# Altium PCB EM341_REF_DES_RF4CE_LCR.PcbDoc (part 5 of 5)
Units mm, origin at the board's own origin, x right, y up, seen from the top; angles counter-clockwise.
Board outline 218.38 x 83.13 mm, 2 copper layers (Top Layer, Carbon Ink Layer); 111 components, 91 nets, 369 pads, 80 vias.
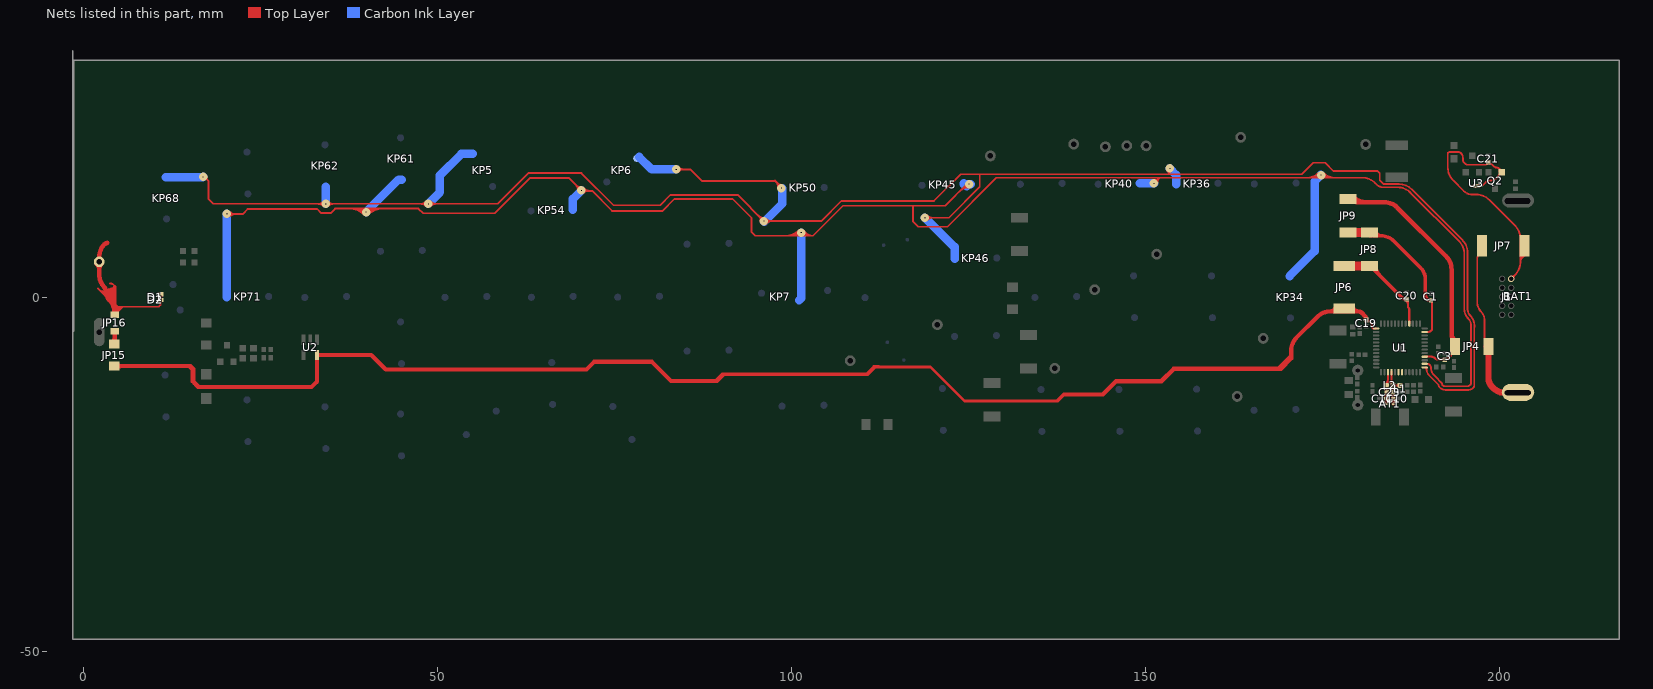
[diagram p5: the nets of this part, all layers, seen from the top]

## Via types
v1: diameter 1.2, hole 0, Top Layer to Carbon Ink Layer, 80 vias

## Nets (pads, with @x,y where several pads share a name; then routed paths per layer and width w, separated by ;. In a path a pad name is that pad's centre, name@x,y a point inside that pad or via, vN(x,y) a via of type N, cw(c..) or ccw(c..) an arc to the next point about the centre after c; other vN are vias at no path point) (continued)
PC6: KP5.1 KP6.2 KP36.1 KP46.2 KP50.2 KP62.2 KP68.2 U1.13 | length 330.2
  Top Layer w0.254: v1(16.87,16.96) 17.07,16.96 17.65,16.38 17.65,13.84 18.32,13.17 58.47,13.17 62.8,17.5 70.3,17.5 74.83,12.97 81.43,12.97 82.88,14.42 92.37,14.42 v1(96.07,10.72) 104.17,10.72 107.01,13.56 120.07,13.56 123.845,17.335 172.035,17.335 173.67,18.97 175.32,18.97 176.5,17.79 182.73,17.79 183.04,17.48 183.04,16.502 183.589,15.953 185.755,15.953 cw(c185.755,13.413) 187.551,15.209 188.826,13.934 188.829,13.934 194.689,8.074 cw(c192.893,6.278) 195.433,6.278 195.433,-1.651 ccw(c196.866,-1.651) 195.853,-2.665 cw(c194.54,-3.977) 196.396,-3.977 196.396,-4.243 ; v1(83.69,18.03) 85.69,18.03 87.32,16.4 97.68,16.4 v1@98.6,15.48 ; v1(118.81,11.2) 122.21,11.2 126.56,15.55 126.56,17.335 ; v1@119.144,10.866 cw(c119.952,10.058) 119.952,11.2 cw(c119.952,12.342) v1@119.144,11.534 ; 153.23,17.335 153.27,17.375 153.27,18.29 v1(153.4,18.16) ; U1.13@189.673,-9.912 cw(c189.642,-9.882) 189.642,-9.925 U1.13@189.378,-9.925 cw(c189.378,-10.249) 189.607,-10.02 cw(c189.522,-10.105) 189.643,-10.105 ccw(c191.07,-10.105) 190.061,-11.114 191.291,-12.344 cw(c191.098,-12.537) 191.371,-12.537 ccw(c191.607,-12.537) 191.44,-12.704 191.54,-12.804 ccw(c192.286,-12.058) 192.286,-13.113 194.743,-13.113 ; 194.76,-13.115 195.552,-13.115 ccw(c195.552,-12.185) 196.21,-12.842 ccw(c195.77,-12.402) 196.392,-12.402 196.392,-4.253 ; 84.832,18.03 cw(c84.832,19.172) 84.024,18.364 ccw(c84.832,19.172) 84.832,18.03 ; 84.832,18.03 ccw(c84.832,16.888) 84.024,17.696 cw(c84.832,16.888) 84.832,18.03 ; 95.263,11.527 cw(c94.455,10.72) 95.597,10.72 ccw(c94.455,10.72) 95.263,11.527 ; 95.263,11.527 ccw(c96.07,12.335) 96.07,11.193 cw(c96.07,12.335) 95.263,11.527 ; 97.212,10.72 cw(c97.212,11.862) 96.404,11.054 ccw(c97.212,11.862) 97.212,10.72 ; 97.212,10.72 ccw(c97.212,9.578) 96.404,10.386 cw(c97.212,9.578) 97.212,10.72 ; 153.27,17.364 cw(c153.623,17.364) 153.528,17.705 ccw(c153.623,17.364) 153.27,17.364 ; 153.27,17.364 ccw(c152.649,17.364) 153.075,17.816 cw(c152.649,17.364) 153.27,17.364 ; v1@16.92,16.747 cw(c17.044,16.219) 17.428,16.602 ccw(c17.044,16.219) v1@16.92,16.747 ; v1@17.343,16.96 ccw(c18.002,16.96) 17.536,16.494 cw(c18.002,16.96) v1@17.343,16.96 ; 33,13.17 cw(c33,11.96) 33.856,12.816 ccw(c33,11.96) 33,13.17 ; 33.096,13.17 ccw(c33.096,14.244) 33.856,13.484 cw(c33.096,14.244) 33.096,13.17 ; v1@34.524,12.816 cw(c35.38,11.96) 35.38,13.17 ccw(c35.38,11.96) v1@34.524,12.816 ; v1@34.524,13.484 ccw(c35.284,14.244) 35.284,13.17 cw(c35.284,14.244) v1@34.524,13.484 ; 47.514,13.17 cw(c47.514,11.994) 48.346,12.826 ccw(c47.514,11.994) 47.514,13.17 ; 47.562,13.17 ccw(c47.562,14.278) 48.346,13.494 cw(c47.562,14.278) 47.562,13.17 ; v1@49.014,12.826 cw(c49.846,11.994) 49.846,13.17 ccw(c49.846,11.994) v1@49.014,12.826 ; v1@49.014,13.494 ccw(c49.798,14.278) 49.798,13.17 cw(c49.798,14.278) v1@49.014,13.494 ; 97.636,16.444 cw(c96.573,15.38) 98.077,15.38 ccw(c96.573,15.38) 97.636,16.444 ; 97.999,16.081 ccw(c98.55,16.633) 98.55,15.853 cw(c98.55,16.633) 97.999,16.081 ; 98.07,16.01 cw(c97.44,15.38) 98.331,15.38 ccw(c97.44,15.38) 98.07,16.01
  Carbon Ink Layer w1.2: KP68.2@11.59,16.937 16.847,16.937 v1(16.87,16.96) ; v1@34.21,13.17 KP62.2@34.21,15.593 ; v1(48.68,13.16) 50.32,14.8 50.32,17.19 53.346,20.216 KP5.1@54.988,20.216 ; KP6.2@78.452,19.792 80.224,18.02 83.7,18.02 v1(83.69,18.03) ; v1@96.14,10.65 98.683,13.193 KP50.2@98.683,15.35 ; v1@118.81,11.19 123.047,6.953 ; KP46.2@123.053,5.38 123.053,7.13 ; v1(153.4,18.16) 153.4,18.13 154.28,17.25 KP36.1@154.28,15.94
  other v1: 34.19,13.15 98.55,15.38
PC7: KP7.2 KP34.2 KP40.2 KP45.2 KP54.2 KP61.2 KP71.2 U1.14 | length 355.5
  Top Layer w0.254: v1@20.634,11.386 cw(c21.442,10.578) 21.442,11.72 ; v1@20.634,12.054 ccw(c21.442,12.862) 21.442,11.72 ; 61.83,15.61 63.05,16.83 ; v1@69.817,15.06 ccw(c68.675,15.06) 69.483,15.867 ccw(c70.29,16.675) v1@70.29,15.533 ; v1(70.29,15.06) 68.52,16.83 63.05,16.83 ; v1@70.37,14.99 71.8,14.99 74.62,12.17 81.76,12.17 83.45,13.86 91.63,13.86 94.33,11.16 94.33,9.17 94.85,8.65 103,8.65 ; v1@70.445,15.215 ccw(c70.988,15.758) 70.988,14.99 ; v1@70.624,14.726 cw(c71.263,14.087) 71.263,14.99 ; v1@70.624,15.394 ccw(c71.601,16.371) 71.601,14.99 ; 117.11,12.89 117.11,10.71 117.89,9.93 121.99,9.93 128.907,16.847 180.586,16.847 cw(c180.586,14.307) 182.382,16.104 182.575,15.91 ccw(c183.568,16.903) 183.568,15.499 185.566,15.499 cw(c185.566,12.959) 187.362,14.755 194.235,7.883 cw(c192.439,6.087) 194.979,6.087 194.979,-1.75 ccw(c196.708,-1.75) 195.485,-2.973 cw(c194.411,-4.047) 195.93,-4.047 195.93,-4.565 ; 123.696,14.916 cw(c125.05,13.563) v1@125.05,15.477 ; 124.13,15.35 cw(c125.05,14.43) v1@125.05,15.731 ; 124.469,15.689 ccw(c124.208,15.95) v1@124.577,15.95 ; v1@125.24,15.96 124.74,15.96 121.67,12.89 107.24,12.89 103,8.65 ; v1(151.15,16.05) 151.14,16.06 151.173,16.06 151.96,16.847 ; v1(174.74,17.23) v1@174.75,17.23 ; U1.14@189.378,-9.425 189.704,-9.425 cw(c189.704,-10.014) 190.12,-9.597 cw(c189.776,-9.942) 190.262,-9.942 ccw(c191.834,-9.942) 190.357,-10.479 ccw(c191.834,-9.942) 190.638,-10.961 ccw(c191.834,-9.942) 190.723,-11.053 190.917,-11.248 ; 190.915,-11.25 191.743,-12.078 cw(c191.478,-12.343) 191.83,-12.215 cw(c191.478,-12.343) 191.852,-12.327 cw(c191.478,-12.343) 191.852,-12.343 191.86,-12.35 ccw(c191.999,-12.35) 191.901,-12.448 ccw(c192.261,-12.088) 192.261,-12.598 194.682,-12.598 ; 194.683,-12.602 195.351,-12.602 ccw(c195.351,-11.954) 195.81,-12.413 ccw(c195.522,-12.124) 195.929,-12.124 195.929,-4.553 ; 21.442,11.72 22.45,11.72 23.16,12.43 33,12.43 33.57,11.86 34.89,11.86 35.52,12.49 47.28,12.49 47.94,11.83 58.05,11.83 63.05,16.83 ; 103,8.65 cw(c103,10.131) 101.742,9.35 ccw(c103,10.131) 103,8.65 ; 151.96,16.847 cw(c151.176,17.631) 151.158,16.523 ccw(c151.176,17.631) 151.96,16.847 ; 37.575,12.49 cw(c37.575,9.675) 39.566,11.666 ccw(c37.575,9.675) 37.575,12.49 ; 38.188,12.49 cw(c38.188,10.288) 39.745,11.845 ccw(c38.188,10.288) 38.188,12.49 ; 38.802,12.49 cw(c38.802,10.902) 39.925,12.025 ccw(c38.802,10.902) 38.802,12.49 ; 39.415,12.49 cw(c39.415,11.515) 40.104,12.204 ccw(c39.415,11.515) 39.415,12.49 ; v1@39.696,12.204 cw(c40.385,11.515) 40.385,12.49 ccw(c40.385,11.515) v1@39.696,12.204 ; v1@39.875,12.025 cw(c40.998,10.902) 40.998,12.49 ccw(c40.998,10.902) v1@39.875,12.025 ; v1@40.055,11.845 cw(c41.612,10.288) 41.612,12.49 ccw(c41.612,10.288) v1@40.055,11.845 ; v1@40.234,11.666 cw(c42.225,9.675) 42.225,12.49 ccw(c42.225,9.675) v1@40.234,11.666 ; 99.112,8.65 ccw(c99.112,11.328) 101.006,9.434 cw(c99.112,11.328) 99.112,8.65 ; 99.725,8.65 ccw(c99.725,10.715) 101.185,9.255 cw(c99.725,10.715) 99.725,8.65 ; 100.338,8.65 ccw(c100.338,10.102) 101.365,9.075 cw(c100.338,10.102) 100.338,8.65 ; v1@101.31,9.082 ccw(c102.086,9.564) 102.086,8.65 cw(c102.086,9.564) v1@101.31,9.082 ; v1@101.526,9.216 ccw(c102.543,9.847) 102.543,8.65 cw(c102.543,9.847) v1@101.526,9.216 ; v1@151.623,16.05 cw(c152.735,16.05) 151.949,16.836 ccw(c152.735,16.05) v1@151.623,16.05 ; 172.675,16.847 ccw(c172.675,19.295) 174.406,17.564 cw(c172.675,19.295) 172.675,16.847 ; 173.288,16.847 ccw(c173.288,18.682) 174.585,17.385 cw(c173.288,18.682) 173.288,16.847 ; 173.901,16.847 ccw(c173.901,18.069) 174.765,17.205 cw(c173.901,18.069) 173.901,16.847 ; v1@174.715,17.205 ccw(c175.579,18.069) 175.579,16.847 cw(c175.579,18.069) v1@174.715,17.205 ; v1@174.895,17.385 ccw(c176.192,18.682) 176.192,16.847 cw(c176.192,18.682) v1@174.895,17.385 ; v1@175.074,17.564 ccw(c176.805,19.295) 176.805,16.847 cw(c176.805,19.295) v1@175.074,17.564
  Carbon Ink Layer w1.2: KP71.2@20.233,-0.04 v1@20.233,11.76 ; v1(39.9,12) 44.483,16.583 KP61.2@44.9,16.583 ; KP54.2@69.11,12.31 69.097,12.31 69.097,13.867 v1(70.29,15.06) ; KP7.2@101.026,-0.466 101.34,-0.151 v1(101.34,9.1) ; KP45.2@124.68,15.66 124.297,16.043 124.297,15.96 v1@125.25,15.96 ; KP40.2@149.177,16.06 151.15,16.06 151.16,16.05 v1(151.15,16.05) ; KP34.2@170.3,2.957 173.83,6.487 173.83,16.34 174.73,17.24 v1(174.74,17.23)
  other v1: 20.24,11.76 125.05,15.95
RF_N: AT1.2 C10.1 C23.2 L1.1 L2.1 U1.4 | length 14.5
  Top Layer w0.292: U1.4@184.703,-10.49 U1.4@184.703,-10.6 184.703,-12.078 ; L2.1@184.744,-12.372 ccw(c184.53,-12.252) 184.703,-12.078 ; L2.1@184.917,-12.475 184.931,-12.489 L1.1@185.898,-12.489 ; L2.1@185.03,-12.405 184.703,-12.078 ; 184.703,-12.078 ccw(c184.905,-12.078) L2.1@184.903,-12.28 ; 184.703,-12.078 ccw(c184.905,-12.078) L2.1@184.903,-12.28 ; 184.703,-12.078 ccw(c184.905,-12.078) L2.1@184.903,-12.28 ; 184.703,-11.551 ccw(c185.808,-11.551) L2.1@185.027,-12.332 ; 184.703,-11.551 ccw(c185.808,-11.551) L2.1@185.027,-12.332 ; 184.703,-11.551 ccw(c185.808,-11.551) L2.1@185.027,-12.332 ; L2.1@185.027,-12.611 cw(c185.32,-12.904) 185.32,-12.489 ; L2.1@185.027,-12.611 cw(c185.32,-12.904) 185.32,-12.489 ; L2.1@185.027,-12.611 cw(c185.32,-12.904) 185.32,-12.489 ; L2.1@185.027,-12.357 ccw(c185.344,-12.04) 185.344,-12.489 ; L2.1@185.027,-12.357 ccw(c185.344,-12.04) 185.344,-12.489 ; L2.1@185.027,-12.357 ccw(c185.344,-12.04) 185.344,-12.489 ; 185.441,-12.489 cw(c185.441,-12.921) L1.1@185.746,-12.616 ; 185.441,-12.489 ccw(c185.441,-12.057) L1.1@185.746,-12.362 ; 185.441,-12.489 cw(c185.441,-12.921) L1.1@185.746,-12.616 ; 185.441,-12.489 ccw(c185.441,-12.057) L1.1@185.746,-12.362 ; 185.441,-12.489 ccw(c185.441,-12.057) L1.1@185.746,-12.362 ; 185.441,-12.489 cw(c185.441,-12.921) L1.1@185.746,-12.616
  Top Layer w0.508: C10.1@184.9,-14.182 L2.1@184.9,-12.484 L2.1@184.9,-12.475 ; AT1.2@184.95,-15.092 184.95,-14.405 C10.1@185.017,-14.337 ; 184.9,-13.987 ccw(c185.354,-13.987) C10.1@185.033,-14.307 ; 184.9,-13.987 ccw(c185.354,-13.987) C10.1@185.033,-14.307 ; 184.9,-13.987 ccw(c185.354,-13.987) C10.1@185.033,-14.307
RF_P: AT1.1 C11.1 C23.1 L2.2 U1.3 | length 10.2
  Top Layer w0.292: L2.2@184.002,-12.263 184.203,-12.062 ; U1.3@184.203,-10.62 184.203,-12.062 ; L2.2@183.874,-12.332 ccw(c183.078,-11.537) 184.203,-11.537 ; L2.2@183.874,-12.332 ccw(c183.078,-11.537) 184.203,-11.537 ; L2.2@183.874,-12.332 ccw(c183.078,-11.537) 184.203,-11.537 ; L2.2@183.993,-12.28 ccw(c183.985,-12.062) 184.203,-12.062 ; L2.2@183.993,-12.28 ccw(c183.985,-12.062) 184.203,-12.062 ; L2.2@183.993,-12.28 ccw(c183.985,-12.062) 184.203,-12.062 ; L2.2@184.158,-12.374 cw(c184.39,-12.248) 184.203,-12.062 ; L2.2@184.158,-12.374 cw(c184.39,-12.248) 184.203,-12.062 ; L2.2@184.158,-12.374 cw(c184.39,-12.248) 184.203,-12.062
  Top Layer w0.508: C11.1@183.935,-14.248 184,-14.182 L2.2@184,-12.484 L2.2@184,-12.425 ; AT1.1@183.945,-15.021 183.945,-14.24 C11.1@183.998,-14.188 ; C11.1@183.866,-14.309 ccw(c183.543,-13.986) 184,-13.986 ; C11.1@183.866,-14.309 ccw(c183.543,-13.986) 184,-13.986 ; C11.1@183.866,-14.309 ccw(c183.543,-13.986) 184,-13.986
TX_ALT_N: U1.7
TX_ALT_P: U1.6
VDD: BAT1.1 JP4.1 JP7.2 pad.22 pad.23 pad.24 pad.25 pad.26 pad.27 pad.28 pad.29 pad.30 pad.31 pad.32 pad.33 pad.34 pad.35 pad.36 pad.37 pad.38 pad.39 pad.40 pad.41 pad.42 pad.43 pad.44 pad.45 pad.46 pad.47 pad.48 pad.49 pad.50 | length 41.1
  Top Layer w0.254: JP7.2@196.905,8.587 ccw(c197.024,8.587) 196.94,8.502 cw(c196.481,8.044) 197.13,8.044 197.13,6.102 ccw(c197.94,5.293) 196.795,5.293 196.795,-0.652 ccw(c198.956,-0.652) 197.427,-2.18 cw(c196.498,-3.11) 197.812,-3.11 197.812,-5.606 ccw(c198.491,-5.606) 198.011,-6.086 cw(c197.115,-6.983) JP4.1@198.382,-6.983 ; JP7.2@196.952,8.591 cw(c196.038,7.678) JP7.2@197.33,7.678
  Top Layer w0.6: BAT1.1@202.25,-13.475 BAT1.1@202.3,-13.475
  Top Layer w0.635: BAT1.1@201.925,-13.613 BAT1.1@202,-13.613 ; BAT1.1@201.358,-13.442 ccw(c201.771,-13.029) BAT1.1@201.771,-13.613 ; BAT1.1@201.358,-13.442 ccw(c201.771,-13.029) BAT1.1@201.771,-13.613 ; BAT1.1@201.358,-13.442 ccw(c201.771,-13.029) BAT1.1@201.771,-13.613 ; BAT1.1@201.358,-13.442 ccw(c201.771,-13.029) BAT1.1@201.771,-13.613 ; BAT1.1@201.433,-13.442 ccw(c201.846,-13.029) BAT1.1@201.846,-13.613 ; BAT1.1@201.433,-13.442 ccw(c201.846,-13.029) BAT1.1@201.846,-13.613 ; BAT1.1@201.433,-13.442 ccw(c201.846,-13.029) BAT1.1@201.846,-13.613 ; BAT1.1@201.433,-13.442 ccw(c201.846,-13.029) BAT1.1@201.846,-13.613 ; BAT1.1@202.129,-13.613 ccw(c202.129,-13.029) BAT1.1@202.542,-13.442 ; BAT1.1@202.129,-13.613 ccw(c202.129,-13.029) BAT1.1@202.542,-13.442 ; BAT1.1@202.129,-13.613 ccw(c202.129,-13.029) BAT1.1@202.542,-13.442 ; BAT1.1@202.129,-13.613 ccw(c202.129,-13.029) BAT1.1@202.542,-13.442
  Top Layer w0.762: BAT1.1@202.425,-13.456 BAT1.1@202.556,-13.456
  Top Layer w0.889: JP4.1@198.145,-6.973 198.145,-6.981 JP4.1@198.146,-6.995 ; JP4.1@198.437,-6.965 ccw(c198.57,-7.098) 198.382,-7.098 198.382,-11.377 ccw(c200.303,-11.377) 198.945,-12.735 198.999,-12.789 ccw(c200.795,-10.993) 200.795,-13.533 201.6,-13.533 BAT1.1@201.885,-13.533 ; BAT1.1@201.36,-13.64 BAT1.1@201.375,-13.655 ; BAT1.1@201.375,-13.303 BAT1.1@201.53,-13.303 ; BAT1.1@201.731,-13.303 cw(c201.731,-13.869) BAT1.1@202.131,-13.469 ; BAT1.1@201.731,-13.303 cw(c201.731,-13.869) BAT1.1@202.131,-13.469 ; BAT1.1@201.731,-13.303 cw(c201.731,-13.869) BAT1.1@202.131,-13.469 ; BAT1.1@201.731,-13.303 cw(c201.731,-13.869) BAT1.1@202.131,-13.469 ; BAT1.1@201.881,-13.303 cw(c201.881,-13.869) BAT1.1@202.281,-13.469 ; BAT1.1@201.881,-13.303 cw(c201.881,-13.869) BAT1.1@202.281,-13.469 ; BAT1.1@201.881,-13.303 cw(c201.881,-13.869) BAT1.1@202.281,-13.469 ; BAT1.1@201.881,-13.303 cw(c201.881,-13.869) BAT1.1@202.281,-13.469 ; BAT1.1@201.931,-13.303 cw(c201.931,-13.869) BAT1.1@202.331,-13.469 ; BAT1.1@201.931,-13.303 cw(c201.931,-13.869) BAT1.1@202.331,-13.469 ; BAT1.1@201.931,-13.303 cw(c201.931,-13.869) BAT1.1@202.331,-13.469 ; BAT1.1@201.931,-13.303 cw(c201.931,-13.869) BAT1.1@202.331,-13.469 ; BAT1.1@201.931,-13.303 cw(c201.931,-13.869) BAT1.1@202.331,-13.469 ; BAT1.1@201.931,-13.303 cw(c201.931,-13.869) BAT1.1@202.331,-13.469 ; BAT1.1@201.931,-13.303 cw(c201.931,-13.869) BAT1.1@202.331,-13.469 ; BAT1.1@201.931,-13.303 cw(c201.931,-13.869) BAT1.1@202.331,-13.469 ; BAT1.1@201.556,-13.303 cw(c201.556,-13.869) 201.956,-13.469 ccw(c201.556,-13.869) BAT1.1@201.556,-13.303 ; BAT1.1@201.631,-13.303 cw(c201.631,-13.869) 202.031,-13.469 ccw(c201.631,-13.869) BAT1.1@201.631,-13.303
VDD_1: JP15.2 JP16.1 | length 4.3
  Top Layer w0.635: JP16.1@4.365,-4.812 4.365,-6.494 ccw(c4.433,-6.494) JP15.2@4.385,-6.542 ; JP15.2@4.107,-6.41 ccw(c3.485,-5.788) 4.365,-5.788 cw(c3.485,-5.788) JP15.2@4.107,-6.41 ; 4.365,-5.897 ccw(c5.091,-5.897) 4.578,-6.41 cw(c5.091,-5.897) 4.365,-5.897
VDD_2: JP16.2 pad.0@2.2,4.975 | length 32.9
  Top Layer w0.254: 1.99,1.22 4.31,-1.1 4.31,-1.74 ; 2.61,0.86 2.79,0.68 2.79,0.57 ; 3.45,0.22 3.45,1.01 ; 3.56,-0.06 3.56,1.14 ; 3.69,0.18 3.7,0.19 3.7,1.13 ; 3.7,-0.23 3.7,0.42 ; 3.7,1.91 3.94,1.91 4.01,1.84 4.13,1.84 4.52,1.45 JP16.2@4.52,-2.203 ; 3.89,-0.27 3.89,1.19 ; 4.06,-0.57 4.06,1.26 ; 4.3,-0.96 4.3,1.52
  Top Layer w0.635: pad.0@2.2,4.975 2.2,3.187 ccw(c4.74,3.187) 2.944,1.391 cw(c2.609,1.057) 3.083,1.057 ccw(c5.338,1.057) 3.743,-0.538 cw(c2.344,-1.937) 4.323,-1.937 JP16.2@4.323,-2.55 ; pad.0@2.207,5.01 2.207,5.665 cw(c4.747,5.665) 2.951,7.461 2.955,7.465 cw(c3.371,7.049) 3.371,7.638 ; 2.2,3.902 cw(c3.273,3.902) 2.514,4.661 ccw(c3.273,3.902) 2.2,3.902 ; 2.2,3.902 ccw(c1.127,3.902) 1.886,4.661 cw(c1.127,3.902) 2.2,3.902
VDD_3: C1.1 JP8.2 JP9.1 U1.23 | length 24.8
  Top Layer w0.292: U1.23@189.378,-4.925 189.853,-4.925 ccw(c189.853,-4.268) 190.318,-4.733 ccw(c190.025,-4.44) 190.438,-4.44 190.438,-1.015 ccw(c189.565,-1.015) C1.1@190.183,-0.397
  Top Layer w0.508: JP8.2@181.522,9.02 ccw(c182.422,9.919) 182.422,8.648 183.226,8.648 ; 189.482,2.525 ccw(c187.267,2.525) 188.834,4.092 185.022,7.904 ccw(c183.226,6.108) 183.226,8.648 ; 189.483,2.525 189.483,0.22 ccw(c190.137,0.22) 189.675,-0.242 ccw(c190.049,0.132) 190.049,-0.397 C1.1@190.183,-0.397 ; 183.226,8.648 cw(c183.226,9.403) 182.496,9.208 ccw(c183.226,9.403) 183.226,8.648
  Top Layer w1.27: JP9.1@178.597,9.128 181.573,9.128 cw(c181.573,8.948) JP8.2@181.7,9.075
VDD_4: C3.1 JP4.2 JP9.2 U1.16 | length 41.2
  Top Layer w0.292: U1.16@189.378,-8.425 190.299,-8.425 cw(c190.299,-9.176) 190.83,-8.645 ccw(c191.283,-8.192) 191.283,-8.832 C3.1@192.213,-8.832 ; C3.1@192.202,-8.828 ccw(c192.202,-8.519) 192.42,-8.737 192.429,-8.729 cw(c192.83,-9.13) 192.523,-8.652 ccw(c192.523,-8.157) 192.874,-8.507 193.034,-8.348 ccw(c192.934,-8.247) 193.075,-8.247 ccw(c192.984,-8.157) 193.112,-8.157 193.112,-7.827 cw(c193.539,-7.827) JP4.2@193.238,-7.525 ; 191.818,-8.832 ccw(c191.818,-8.444) 192.093,-8.719 cw(c191.818,-8.444) 191.818,-8.832 ; 191.843,-8.832 cw(c191.843,-9.187) 192.093,-8.936 ccw(c191.843,-9.187) 191.843,-8.832
  Top Layer w0.635: JP9.2@178.788,13.745 179.008,13.745 cw(c179.008,12.823) 179.575,13.55 cw(c179.008,12.823) 179.66,13.475 ccw(c179.901,13.716) 179.901,13.375 ; JP4.2@193.682,-6.983 193.682,-6.605 ccw(c192.445,-6.605) 193.32,-5.73 cw(c193.677,-5.373) 193.172,-5.373 193.172,3.933 ccw(c190.632,3.933) 192.428,5.729 185.526,12.631 ccw(c183.73,10.835) 183.73,13.375 179.901,13.375 ; 179.901,13.375 cw(c179.901,13.841) 179.435,13.839 ccw(c179.901,13.841) 179.901,13.375 ; JP9.2@179.323,14.108 ccw(c181.093,15.878) 181.093,13.375 cw(c181.093,15.878) JP9.2@179.323,14.108
VDD_5: C19.1 JP6.2 JP15.1 U1.37 U2.5 | length 389.5
  Top Layer w0.254: 11.04,-9.745 14.895,-9.745 15.53,-10.38 15.53,-12.27 ; 12.58,-9.745 12.755,-9.57 15.17,-9.57 15.71,-10.11 15.71,-11.89 16.36,-12.54 ; 12.93,-9.92 14.85,-9.92 15.24,-10.31 15.24,-11.98 16.14,-12.88 16.96,-12.88 ; 15.59,-10.23 15.06,-9.7 15.05,-9.7 15.4,-10.05 15.4,-11.81 16.13,-12.54 ; 15.8,-12.54 16.7,-12.54 16.87,-12.71 17.12,-12.71 ; 16.11,-12.69 16.23,-12.69 ; 29.66,-12.7 29.7,-12.7 29.69,-12.71 ; 89.19,-11.74 90.13,-10.8 110.49,-10.8 111.55,-9.74 112.36,-9.74 112.41,-9.79 ; 89.25,-12.02 89.47,-12.02 90.45,-11.04 110.73,-11.04 111.81,-9.96 119.63,-9.96 124.43,-14.76 137.57,-14.76 138.33,-14 ; 89.33,-11.85 90.14,-11.04 ; 90.01,-10.92 110.55,-10.92 111.68,-9.79 119.6,-9.79 124.38,-14.57 137.41,-14.57 138.4,-13.58 143.84,-13.58 145.73,-11.69 152.12,-11.69 153.86,-9.95 169.24,-9.95 169.24,-9.72 170.35,-8.61 ; 140.13,-13.92 144.02,-13.92 145.86,-12.08 152.24,-12.08 154.01,-10.31 169.15,-10.31 170.71,-8.75 170.71,-7.49 ; 140.14,-13.8 143.94,-13.8 145.84,-11.9 152.28,-11.9 154.03,-10.15 ; 152.09,-11.9 153.84,-10.15 169.04,-10.15 170.54,-8.65 170.54,-7.529 ; 168.64,-9.95 170.37,-8.22 ; 168.9,-9.91 170.37,-8.44 170.37,-7.38
  Top Layer w0.292: C19.1@181.22,-3.41 181.462,-3.41 ; U1.37@182.528,-4.425 182.12,-4.425 181.996,-4.301 cw(c182.107,-4.19) 181.95,-4.19 181.95,-4.048 ccw(c181.302,-4.048) 181.76,-3.59 181.664,-3.493 ccw(c181.462,-3.695) 181.462,-3.41 ; 181.462,-3.41 cw(c181.462,-3.213) 181.268,-3.24 ccw(c181.462,-3.213) 181.462,-3.41 ; 182.05,-4.355 ccw(c182.211,-4.194) 182.228,-4.421 cw(c182.211,-4.194) 182.05,-4.355
  Top Layer w0.5: 137.79,-14.36 138.35,-13.8 140.14,-13.8
  Top Layer w0.6: JP15.1@4.343,-9.745 13.475,-9.745 ; 16.44,-12.71 29.69,-12.71 ; 21.12,-12.7 32.2,-12.7 32.954,-11.946 U2.5@32.954,-8.187 40.617,-8.187 42.66,-10.23 71.01,-10.23 72.09,-9.15 80.25,-9.15 82.95,-11.85 89.33,-11.85 ; 170.54,-7.529 cw(c173.08,-7.529) 171.284,-5.733 174.243,-2.774 cw(c176.039,-4.57) 176.039,-2.03 ; C19.1@181.118,-3.161 ccw(c181.094,-3.137) C19.1@181.127,-3.137 ; C19.1@181.165,-3.227 ccw(c180.374,-3.227) 180.933,-2.668 180.486,-2.221 ccw(c180.025,-2.682) 180.025,-2.03 ; 5.287,-9.745 cw(c5.287,-8.9) 4.69,-9.498 ccw(c5.287,-8.9) 5.287,-9.745 ; 5.287,-9.745 ccw(c5.287,-10.59) 4.69,-9.992 cw(c5.287,-10.59) 5.287,-9.745 ; 176.039,-2.03 ccw(c176.039,-1.175) 176.842,-1.47 cw(c176.039,-1.175) 176.039,-2.03 ; 176.039,-2.03 180.025,-2.03 ; 180.025,-2.03 cw(c180.025,-1.133) 179.19,-1.461 ccw(c180.025,-1.133) 180.025,-2.03 ; 180.861,-2.596 cw(c180.246,-3.21) C19.1@181.115,-3.21 ; 180.861,-2.596 cw(c180.246,-3.21) C19.1@181.115,-3.21 ; 180.861,-2.596 cw(c180.246,-3.21) C19.1@181.115,-3.21 ; 180.861,-2.596 cw(c180.246,-3.21) C19.1@181.115,-3.21
VDD_6: C20.1 JP6.1 JP8.1 U1.28 | length 20.3
  Top Layer w0.292: JP6.1@178.018,4.393 cw(c178.018,2.618) JP6.1@179.272,3.873 ; C20.1@187.022,-0.457 187.022,-1.334 ccw(c187.321,-1.334) 187.11,-1.545 cw(c186.885,-1.77) 187.203,-1.77 U1.28@187.203,-3.75 ; C20.1@186.731,-0.421 cw(c186.028,-1.125) 187.022,-1.125 ccw(c186.028,-1.125) C20.1@186.731,-0.421
  Top Layer w0.508: JP8.1@181.484,4.393 ccw(c181.947,4.43) 181.619,4.101 181.718,4.002 cw(c181.718,3.09) 182.363,3.735 186.177,-0.079 ccw(c186.704,0.447) 186.704,-0.298 C20.1@186.868,-0.298 ; JP8.1@182.511,4.393 ccw(c184.455,4.393) 183.08,3.018 cw(c184.455,4.393) JP8.1@182.511,4.393
  Top Layer w0.635: JP6.1@177.995,4.012 ccw(c177.995,4.132) JP6.1@178.08,4.048
  Top Layer w1.27: JP6.1@178.018,4.393 181.484,4.393 181.524,4.393 ccw(c181.524,4.461) JP8.1@181.572,4.413
VDD_7: D1.1 D1.4 D2.1 | length 22.5
  Top Layer w0.254: 4.3,-0.81 4.85,-1.36 6.22,-1.36 ; 4.34,-1.36 7.43,-1.36 ; 4.59,-2.3 5.53,-1.36 6.38,-1.36 ; 4.6,-1.82 4.88,-1.54 4.68,-1.54 4.53,-1.69 4.53,-2.1 5.27,-1.36 5.34,-1.36 ; 6.68,-1.36 7.98,-1.36 ; 7.73,-1.36 10.61,-1.36 10.85,-1.12 D1.1@10.85,0.4 ; D1.4@10.728,-0.522 cw(c10.432,-0.818) 10.85,-0.818 ; D1.4@10.728,-0.522 cw(c10.432,-0.818) 10.85,-0.818 ; D1.4@10.728,-0.522 cw(c10.432,-0.818) 10.85,-0.818 ; D1.4@10.728,-0.522 cw(c10.432,-0.818) 10.85,-0.818 ; D1.4@10.728,-0.278 ccw(c10.432,0.018) 10.85,0.018 ; D1.4@10.728,-0.278 ccw(c10.432,0.018) 10.85,0.018 ; D1.4@10.728,-0.278 ccw(c10.432,0.018) 10.85,0.018 ; D1.4@10.728,-0.278 ccw(c10.432,0.018) 10.85,0.018 ; 10.85,-0.818 cw(c11.268,-0.818) D1.4@10.972,-0.522 ; 10.85,-0.818 cw(c11.268,-0.818) D1.4@10.972,-0.522 ; 10.85,-0.818 cw(c11.268,-0.818) D1.4@10.972,-0.522 ; 10.85,-0.818 cw(c11.268,-0.818) D1.4@10.972,-0.522 ; 10.85,-0.018 cw(c11.268,-0.018) 10.972,0.278 ccw(c11.268,-0.018) 10.85,-0.018 ; 10.85,-0.018 ccw(c10.432,-0.018) 10.728,0.278 cw(c10.432,-0.018) 10.85,-0.018 ; 10.85,0.018 ccw(c11.268,0.018) D1.4@10.972,-0.278 ; 10.85,0.018 ccw(c11.268,0.018) D1.4@10.972,-0.278 ; 10.85,0.018 ccw(c11.268,0.018) D1.4@10.972,-0.278 ; 10.85,0.018 ccw(c11.268,0.018) D1.4@10.972,-0.278
  Top Layer w0.508: D1.1@10.855,0.221 cw(c11.077,0.221) D1.1@10.92,0.377
VDD_8: C21.1 J1.1 JP7.1 Q2.1 U3.3 | length 52.1
  Top Layer w0.254: 196.488,14.477 196.505,14.477 ; 196.488,14.49 196.067,14.49 cw(c196.067,16.132) 195.388,14.637 cw(c196.067,16.132) 194.906,14.971 193.394,16.483 cw(c195.19,18.279) 192.65,18.279 192.65,20.33 cw(c192.693,20.33) 192.662,20.36 cw(c192.946,20.076) 192.946,20.478 194.157,20.478 cw(c194.157,20.017) 194.482,20.342 194.502,20.323 cw(c193.849,19.67) 194.773,19.67 194.773,19.394 ccw(c195.421,19.394) 194.963,18.935 ccw(c195.596,19.569) 195.596,18.673 197.875,18.673 ccw(c197.875,19.287) 198.31,18.853 198.323,18.865 cw(c198.382,18.806) 198.382,18.89 cw(c198.382,18.105) 198.937,18.66 199.14,18.458 ccw(c199.562,18.88) 199.562,18.283 cw(c199.562,17.89) 199.84,18.168 200.035,17.972 cw(c198.417,17.972) 199.561,16.829 cw(c198.665,17.725) 198.665,16.458 ccw(c198.665,15.492) 197.982,16.175 197.639,15.831 cw(c197.267,16.203) U3.3@197.267,15.677 ; 196.505,14.475 196.69,14.475 cw(c196.69,11.935) 197.22,14.419 cw(c196.69,11.935) 198.487,13.731 202.149,10.069 cw(c200.352,8.273) 202.892,8.273 202.892,4.925 cw(c200.352,4.925) 202.149,3.129 J1.1@201.585,2.565 ; U3.3@196.722,15.66 cw(c196.765,15.618) 196.765,15.677 U3.3@197.267,15.677 ; 199.795,18.212 cw(c199.397,17.814) Q2.1@199.951,17.71 ; 199.869,18.139 ccw(c200.268,18.538) Q2.1@200.268,17.973 ; U3.3@197.267,15.677 cw(c197.267,16.011) 197.024,15.783 ccw(c197.267,16.011) U3.3@197.267,15.677 ; U3.3@197.267,15.677 ccw(c197.267,15.389) 197.036,15.562 cw(c197.267,15.389) U3.3@197.267,15.677 ; J1.1@201.585,2.888 ccw(c201.585,3.668) 202.136,3.116 ; J1.1@201.585,2.888 ccw(c201.585,3.668) 202.136,3.116 ; J1.1@201.585,2.888 ccw(c201.585,3.668) 202.136,3.116 ; J1.1@201.908,2.565 cw(c202.688,2.565) 202.136,3.116 ; J1.1@201.908,2.565 cw(c202.688,2.565) 202.136,3.116 ; J1.1@201.908,2.565 cw(c202.688,2.565) 202.136,3.116 ; 202.892,4.818 cw(c204.041,4.818) 203.662,5.902 ccw(c204.041,4.818) 202.892,4.818 ; 202.892,5.176 cw(c203.916,5.176) 203.578,6.141 ccw(c203.916,5.176) 202.892,5.176 ; 202.892,5.534 cw(c203.791,5.534) 203.494,6.381 ccw(c203.791,5.534) 202.892,5.534 ; JP7.1@202.892,5.891 cw(c203.665,5.891) 203.41,6.621 ccw(c203.665,5.891) JP7.1@202.892,5.891
pads on no net: D1.3
copper on no net: | length 4
  Top Layer w0.254: 18.699,-11.73 20.27,-11.73 ; 26.425,-11.725 26.425,-11.125 26.425,-9.3

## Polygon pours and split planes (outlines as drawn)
VDD on Top Layer "Top Layer-VDD" (solid, remove dead copper, pour order 2): 0.7,9.675 0.7,0 5.35,0 5.35,11.775 2.5,11.775 0.6,9.875
NetD3_K on Top Layer "Top Layer-NetD3_K" (solid, remove dead copper, pour order 4): 1.08,-0.482 1.08,-8.557 3.605,-8.557 3.605,-0.357
GND on Top Layer "Top Layer-No Net" (solid, remove dead copper, pour order 5): 153.123,-25.336 189.725,-25.336 cw(c189.725,-25.464) 189.815,-25.373 195.3,-23.303 201.433,-19.223 206.31,-14.251 206.255,14.907 201.148,19.899 198.13,22.007 194.655,24.077 189.89,25.937 189.89,16.862 196.648,8.872 196.668,-10.453 153.123,-10.453

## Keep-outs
Keep-Out Layer:
  circle w0.127: c128.463,12.855 r1.5
  circle w0.127: c39.756,-12.973 r1.5
  circle w0.127: c141.752,-8.552 r1.15
  circle w0.127: c28.906,9.267 r1.15
  circle w0.127: c141.752,8.586 r1.15
  circle w0.127: c28.906,-9.213 r1.15
  lines w0.127: 195.852,23.209 194.067,24.111 192.476,24.818 191.018,25.392 189.421,25.946 142.959,25.946 ; 195.875,23.2 197.975,21.975 ; 197.973,21.973 201,19.829 ; 7.235,19.638 13.753,23.598 ; 7.235,19.638 0.016,9.938 0.016,-9.904 7.208,-19.568 13.753,-23.544 22.692,-25.889 64.47,-25.889 94.832,-21.614 ; 7.235,19.638 13.753,23.598 ; 13.753,23.598 22.703,25.946 ; 13.753,23.598 22.703,25.946 ; 22.703,25.946 64.308,25.946 94.832,21.648 ; 94.832,-21.614 94.832,-21.008 ; 94.832,-21.614 94.832,-21.008 ; 94.832,-21.008 100.336,-20.233 ; 94.832,-21.008 100.336,-20.233 ; 94.832,21.042 94.832,21.648 ; 94.832,21.042 100.358,20.264 ; 94.832,21.042 100.358,20.264 ; 94.832,21.042 94.832,21.648 ; 100.336,-20.233 105.817,-20.611 ; 100.336,-20.233 105.817,-20.611 ; 100.358,20.264 105.817,20.638 ; 100.358,20.264 105.817,20.638 ; 105.817,-21.513 105.817,-20.611 ; 105.817,-21.513 105.817,-20.611 ; 105.817,-21.513 124.105,-22.774 141.19,-25.889 189.491,-25.889 ; 105.817,20.638 105.817,21.542 ; 105.817,20.638 105.817,21.542 ; 105.817,21.542 124.064,22.8 ; 105.817,21.542 124.064,22.8 ; 124.064,22.8 138.28,25.391 ; 124.064,22.8 138.28,25.391 ; 138.28,25.391 142.959,25.946 ; 138.28,25.391 142.959,25.946 ; 189.491,-25.889 189.986,-25.725 ; 189.491,-25.889 189.986,-25.725 ; 189.986,-25.725 190.641,-25.496 ; 189.986,-25.725 190.641,-25.496 ; 190.641,-25.496 191.286,-25.258 ; 190.641,-25.496 191.286,-25.258 ; 191.286,-25.258 191.922,-25.01 192.549,-24.753 193.167,-24.487 193.777,-24.212 194.377,-23.929 194.969,-23.637 195.552,-23.336 196.126,-23.026 196.692,-22.708 197.25,-22.382 197.799,-22.048 198.34,-21.704 198.872,-21.353 199.396,-20.993 199.912,-20.625 200.418,-20.247 200.916,-19.862 201.406,-19.467 201.886,-19.064 202.358,-18.651 202.821,-18.23 203.274,-17.8 203.719,-17.361 204.155,-16.913 204.581,-16.456 204.999,-15.989 205.406,-15.513 205.804,-15.027 206.167,-14.563 206.167,-1.983 205.056,-1.983 cw(c205.056,0.017) 205.056,2.017 206.167,2.017 206.167,14.597 205.939,14.89 ; 201,19.829 205.939,14.89 ; 201,19.829 205.939,14.89
  text "Keep-Out Layer" at 1.495,-37.765 h2

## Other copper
Top Layer:
  rectangle net GND: 204.58,2.32 205.11,2.97
  region net GND: 206,2.28 206,5.56 205.11,5.56 205.11,2.28
  rectangle net GND: 204.35,-2.95 205.99,-2.24
  rectangle net GND: 110.71,-21.103 111.213,-20.69
  rectangle net GND: 111.14,-21.201 112.215,-20.78
  rectangle net GND: 126.33,-22.53 127.45,-22.13
  rectangle net GND: 121.41,-21.903 121.93,-21.55
  rectangle net GND: 124.66,-22.18 125.77,-21.6
  rectangle net GND: 121.768,-21.891 128.57,-20.91
  rectangle net GND: 127.99,-22.78 128.59,-22.43
  rectangle net GND: 118.38,-21.683 118.881,-21.38
  rectangle net GND: 112.65,-21.23 114.15,-20.9
  rectangle net GND: 116.24,-21.48 118.98,-20.6
  rectangle net GND: 113.97,-21.32 116.5,-20.88
  rectangle net GND: 112.087,-20.769 114.13,-19.23
  rectangle net GND: 114.41,-20.13 114.76,-19.72
  rectangle net GND: 114.76,-20.5 117.51,-20.13
  rectangle net GND: 114.71,-20.29 115.08,-20.07
  rectangle net GND: 114.38,-20.5 114.91,-19.84
  rectangle net GND: 118.74,-21.74 122.15,-20.58
  rectangle net GND: 125.24,-20.63 125.78,-20.06
  rectangle net GND: 125.08,-21.13 126.08,-20.34
  rectangle net GND: 125.77,-20.99 126.32,-20.53
  rectangle net GND: 117.087,-20.3 117.46,-19.593
  rectangle net GND: 117.25,-19.87 117.6,-19.36
  rectangle net GND: 112.472,-21.05 125.53,-20.2
  rectangle net GND: 3.451,-11.83 4.58,-11.368
  rectangle net GND: 9.52,-8.7 14.75,-7.9
  rectangle net GND: 11.195,-8.09 11.55,-7.465
  rectangle net GND: 11.637,-8.24 13.27,-7.023
  rectangle net GND: 12.67,-8.15 13.78,-6.15
  rectangle net GND: 10.97,-8.01 11.41,-7.69
  rectangle net GND: 11.41,-8.01 11.85,-7.25
  rectangle net GND: 11.904,-7.45 12.38,-6.756
  rectangle net GND: 12.09,-7.19 12.51,-6.55
  rectangle net GND: 12.273,-7.54 13.01,-6.557
  rectangle net GND: 12.424,-6.77 12.93,-6.236
  rectangle net GND: 12.7,-6.47 13.24,-5.96
  rectangle net GND: 12.958,-6.31 13.58,-5.702
  rectangle net GND: 13.19,-5.95 13.66,-5.47
  rectangle net GND: 14.49,-8.57 14.88,-8.39
  rectangle net GND: 14.59,-8.5 14.95,-8.17
  rectangle net GND: 14.75,-8.37 15.08,-8.09
  rectangle net GND: 14.42,-7.944 15.506,-7.6
  rectangle net GND: 14.75,-8.27 15.16,-7.9
  rectangle net GND: 14.92,-8.108 15.342,-7.79
  rectangle net GND: 15.42,-7.83 15.64,-7.66
  rectangle net GND: 27.25,-6.61 30.98,-5.33
  rectangle net GND: 13.417,-8.11 14.51,-5.243
  rectangle net GND: 14.19,-7.74 15.71,-5.223
  rectangle net GND: 58.67,-24.982 65.044,-23.9
  rectangle net GND: 14.07,-22.17 17.098,-20.799
  rectangle net GND: 12.909,-21.335 17.001,-20.346
  rectangle net GND: 11.88,-20.699 16.49,-19.16
  rectangle net GND: 77.879,-22.1 78.72,-21.463
  rectangle net GND: 77.344,-21.98 77.71,-21.773
  rectangle net GND: 77.552,-21.98 78.15,-21.653
  rectangle net GND: 77.71,-21.98 78.15,-21.561
  rectangle net GND: 78.136,-21.77 80.29,-21.313
  rectangle net GND: 78.307,-21.52 78.626,-21.214
  rectangle net GND: 78.626,-21.52 78.99,-21.028
  rectangle net GND: 78.453,-21.45 78.87,-21.129
  rectangle net GND: 78.87,-21.45 79.26,-20.886
  rectangle net GND: 79.083,-21.42 79.83,-20.763
  rectangle net GND: 83.76,-21.851 85.809,-20.89
  rectangle net GND: 85.65,-21.613 87.492,-20.96
  rectangle net GND: 79.488,-21.82 84.13,-20.527
  rectangle net GND: 79.316,-20.99 79.73,-20.628
  rectangle net GND: 79.739,-20.96 80.4,-20.382
  rectangle net GND: 79.907,-20.84 80.7,-20.284
  rectangle net GND: 80.08,-20.71 80.6,-20.184
  rectangle net GND: 80.4,-20.96 81.12,-19.997
  rectangle net GND: 80.215,-20.84 80.7,-20.105
  rectangle net GND: 83.66,-21.277 89.871,-20.46
  rectangle net GND: 89.32,-21.16 91.69,-20.54
  rectangle net GND: 88.83,-20.742 93.662,-19.92
  rectangle net GND: 80.802,-20.92 81.46,-19.764
  rectangle net GND: 80.642,-20.5 81.34,-19.857
  rectangle net GND: 81.12,-20.96 89.55,-19.44
  rectangle net GND: 80.983,-20.41 81.48,-19.659
  rectangle net GND: 107.3,-20.75 111.93,-19.76
  rectangle net GND: 109.04,-20.925 112.18,-20.53
  rectangle net GND: 106.75,-20.707 107.383,-20.19
  rectangle net GND: 107.12,-20.58 107.63,-20
  rectangle net GND: 8.01,-18.309 8.91,-17.203
  rectangle net GND: 7.45,-18.07 8.25,-16.61
  rectangle net GND: 10.61,-20.05 14.57,-18.55
  rectangle net GND: 5.19,-14.6 5.93,-12.3
  rectangle net GND: 6.13,-13.92 6.679,-13.01
  rectangle net GND: 5.99,-13.91 6.562,-12.623
  rectangle net GND: 4.8,-13.98 5.54,-12.07
  rectangle net GND: 5.932,-15.698 6.449,-12.248
  rectangle net GND: 5.6,-14.93 6.335,-11.869
  rectangle net GND: 6.235,-16.107 7.04,-13.7
  rectangle net GND: 6.63,-15.91 7.335,-14.607
  rectangle net GND: 6.63,-15.67 7.186,-14.282
  rectangle net GND: 6.07,-16.19 6.82,-13.48
  rectangle net GND: 6.38,-13.87 6.749,-13.243
  rectangle net GND: 4.49,-13.41 5.11,-12.19
  rectangle net GND: 4.38,-13.27 5.13,-12.39
  rectangle net GND: 6.81,-16.39 7.45,-14.859
  rectangle net GND: 6.7,-15.34 7.261,-14.446
  rectangle net GND: 82.136,-20.21 93.785,-18.705
  rectangle net GND: 81.414,-19.67 81.708,-19.337
  rectangle net GND: 81.528,-19.61 81.97,-19.237
  rectangle net GND: 81.708,-19.67 82.53,-19.079
  rectangle net GND: 81.977,-19.49 82.48,-18.844
  rectangle net GND: 81.854,-19.29 82.16,-18.952
  rectangle net GND: 82.449,-19.15 82.78,-18.431
  rectangle net GND: 82.29,-19.15 82.78,-18.57
  rectangle net GND: 82.61,-19.23 83.34,-18.29
  rectangle net GND: 82.78,-19.15 83.65,-18.04
  rectangle net GND: 82.99,-18.45 98.34,-17.75
  rectangle net GND: 98.34,-18.57 98.78,-18.18
  rectangle net GND: 97.92,-18.32 98.5,-17.85
  rectangle net GND: 123.42,-22.01 124.51,-21.65
  rectangle net GND: 124.33,-22.159 124.707,-21.71
  rectangle net GND: 125.44,-22.34 128.8,-21.57
  rectangle net GND: 128.49,-22.91 137.25,-20.91
  rectangle net GND: 127.17,-22.67 128.77,-22.11
  rectangle net GND: 115.5,-21.5 116.355,-21.13
  rectangle net GND: 117.79,-21.662 118.589,-21.37
  rectangle net GND: 126.05,-21.01 126.447,-20.787
  rectangle net GND: 133.94,-23.89 134.34,-23.62
  rectangle net GND: 132.825,-23.704 133.496,-22.79
  rectangle net GND: 131.69,-23.44 133.05,-22.64
  rectangle net GND: 135.78,-24.33 137.07,-23.96
  rectangle net GND: 137.46,-24.54 137.76,-24.34
  rectangle net GND: 136.64,-24.502 137.023,-24.11
  rectangle net GND: 134.34,-24.03 135.18,-23.59
  rectangle net GND: 133.35,-23.79 135.32,-22.55
  rectangle net GND: 135.105,-24.138 136.93,-22.73
  rectangle net GND: 112.093,-21.239 112.738,-20.382
  rectangle net GND: 113.99,-20.59 114.583,-19.573
  rectangle net GND: 113.91,-19.92 114.44,-19.3
  rectangle net GND: 117.13,-21.02 125.78,-20.06
  rectangle net GND: 125.53,-20.51 125.91,-20.19
  rectangle net GND: 116.91,-20.39 117.28,-19.74
  rectangle net GND: 117.43,-20.6 117.83,-19.25
  rectangle net GND: 116.61,-20.39 116.91,-20.07
  rectangle net GND: 116.73,-20.3 117.087,-19.89
  rectangle net GND: 137.64,-24.67 138.18,-24.38
  rectangle net GND: 137.94,-24.748 138.311,-24.38
  rectangle net GND: 136.93,-24.485 141.6,-22.73
  rectangle net GND: 138.18,-24.67 139.07,-24.4
  rectangle net GND: 138.25,-23.19 157.05,-22.01
  rectangle net GND: 140.2,-25.174 140.553,-24.89
  rectangle net GND: 141.33,-25.366 141.559,-25.14
  rectangle net GND: 140.39,-25.21 141.54,-24.87
  rectangle net GND: 138.54,-24.879 139.002,-24.5
  rectangle net GND: 139.54,-24.99 140.02,-24.78
  rectangle net GND: 138.97,-24.89 140.2,-24.36
  rectangle net GND: 140.02,-24.99 141.64,-24.33
  rectangle net GND: 141.45,-25.44 152.96,-22.73
  rectangle net GND: 152.97,-24.13 156.49,-22.73
  rectangle net GND: 149.86,-22.27 150.22,-21.97
  rectangle net GND: 149.93,-22.12 150.24,-21.82
  rectangle net GND: 150.37,-22.23 150.74,-21.4
  rectangle net GND: 150.08,-22.16 150.62,-21.58
  rectangle net GND: 150.56,-22.47 151.21,-21.22
  rectangle net GND: 150.74,-22.23 151.35,-20.98
  rectangle net GND: 151.01,-22.43 151.98,-20.76
  rectangle net GND: 151.12,-21.02 152.02,-20.36
  rectangle net GND: 151.576,-22.54 152.72,-19.944
  rectangle net GND: 151.96,-20.13 152.77,-19.47
  rectangle net GND: 152.442,-22.61 155.19,-19.078
  rectangle net GND: 152.61,-19.18 153.3,-18.82
  rectangle net GND: 152.98,-19.5 153.59,-18.53
  rectangle net GND: 152.83,-19.34 153.26,-18.68
  rectangle net GND: 153.15,-19.74 153.91,-18.32
  rectangle net GND: 153.34,-19.64 154.14,-18.06
  rectangle net GND: 153.59,-19.18 154.11,-17.92
  rectangle net GND: 153.76,-19.62 154.98,-17.66
  rectangle net GND: 154.57,-22.42 157.33,-16.95
  rectangle net GND: 153.985,-18 154.35,-17.535
  rectangle net GND: 154.112,-17.99 154.47,-17.408
  rectangle net GND: 154.24,-17.98 154.66,-17.27
  rectangle net GND: 154.37,-18.11 154.98,-17.04
  rectangle net GND: 3.597,-12.546 6.23,-11.52
  rectangle net GND: 97.1,-18.76 98.623,-18.033
  rectangle net GND: 125.28,-20.23 125.61,-19.92
  rectangle net GND: 110.867,-20.75 111.93,-19.661
  rectangle net GND: 83.29,-19.5 97.42,-18.08
  rectangle net GND: 172.9,12.51 176.87,15.11
  rectangle net PA5: 148.763,4.703 152.543,6.383
  rectangle net PC3: 153.43,-7.97 164.18,-6.61
  rectangle net GND: 146.238,-14.88 146.86,-13.372
  rectangle net GND: 145.62,-14.88 146.44,-13.95
  region net VDD_2: 1.45,8.3 4.65,9.875 4.65,2.65 4.65,1.375 3.9,0.825 1.7,0.825 1.45,1.375 1.45,1.675 1.45,2.15 1.45,3.025
  text "Top Layer" at 1.495,-37.765 h2
Carbon Ink Layer:
  text "Carbon Ink Layer over Top Layer" at 1.495,-37.765 h2
Multi-Layer:
  text "EM341_REF_DES_RF4CE_LCR_A0" at 130.05,-37.34 h2
  text "EM341 Dipole Antenna RF4CE 1-Layer Remote Control" at 130.05,-41.44 h2

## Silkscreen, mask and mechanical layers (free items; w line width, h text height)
Top Overlay:
  drawing of 4891 lines, arcs and shapes, not listed
  text "JP24" at 179.57,22.91 h0.8
  text "JP25" at 142.246,22.72 h0.8
  text "JP21" at 145.38,22.71 h0.8
  text "JP22" at 148.98,22.71 h0.8
  text "JP27" at 138.37,22.66 h0.8
  text "JP23" at 159.27,21.92 h0.8
  text "JP26" at 129.44,19.92 h0.8
  text "Top Overlay" at 1.495,-37.765 h2
Bottom Overlay:
  text "Bottom Overlay" at 1.495,-37.765 h2
Top Paste:
  text "Top Paste" at 1.495,-37.765 h2
Bottom Paste:
  text "Bottom Paste" at 1.495,-37.765 h2
Top Solder:
  text "Top Solder" at 1.495,-37.765 h2
Bottom Solder:
  text "Bottom Solder" at 1.495,-37.765 h2
Mechanical 1:
  drawing of 406 lines, arcs and shapes, not listed
  text "SMD LED" at 7.35,-6 h0.8
  text "1608" at 8.55,-7.3 h0.8
  text "Top Assembly" at 1.495,-38.095 h2
Mechanical 2:
  lines w0.254: 108.18,-9.06 119.93,7.69 125.68,15.09 127.93,19.88 ; 120.58,-4.05 130.65,12.2 139.62,21.59 ; 137.34,-9 139.043,-1.45 142.448,13.65 144.15,21.2 ; 142.77,0.94 147.31,21.37 ; 149.843,21.43 151.54,6.06 ; 162.73,-13.41 162.22,-3 163.277,21.399 ; 166.58,-5.84 177.2,15.08 181.04,21.55
  text "JP27" at 138.56,21.07 h0.8
  text "JP23" at 162.41,20.5 h0.8
  text "JP24" at 179.45,20.5 h0.8
  text "JP22" at 153.15,19.6 h0.8
  text "JP25" at 143.23,19.27 h0.8
  text "JP26" at 126.77,18.7 h0.8
  text "JP21" at 149.05,15.34 h0.8
  text "BAT1" at 200.21,15.11 h0.8 r90
  text "J1" at 201.37,0.65 h0.8 r90
  text "D3" at 1.7,-0.58 h0.8 r270
  text "BAT1" at 200.16,-12 h0.8 r90
  text "Y1" at 180.21,-12.04 h0.8 r90
  text "Bottom Assembly" at 27.96,-37.34 h2
Board Outline 7:
  lines w0.127: 7.235,19.638 0.016,9.938 0.016,-9.904 7.208,-19.568 13.753,-23.544 22.692,-25.889 64.47,-25.889 94.832,-21.614 ; 22.703,25.946 64.308,25.946 94.832,21.648 ; 105.817,-21.513 124.105,-22.774 141.19,-25.889 189.491,-25.889 ; 142.959,25.946 189.421,25.946 191.018,25.392 192.476,24.818 194.067,24.111 195.852,23.209 ; 191.286,-25.258 191.922,-25.01 192.549,-24.753 193.167,-24.487 193.777,-24.212 194.377,-23.929 194.969,-23.637 195.552,-23.336 196.126,-23.026 196.692,-22.708 ; 197.25,-22.382 197.799,-22.048 198.34,-21.704 ; 197.973,21.973 201,19.829 ; 198.872,-21.353 199.396,-20.993 199.912,-20.625 200.418,-20.247 200.916,-19.862 201.406,-19.467 201.886,-19.064 202.358,-18.651 202.821,-18.23 203.274,-17.8 203.719,-17.361 204.155,-16.913 204.581,-16.456 204.999,-15.989 205.406,-15.513 205.804,-15.027 206.167,-14.563 206.167,-1.983 205.056,-1.983 ; 201.15,-19.625 201.2,-19.625 ; 205.056,2.017 206.167,2.017 206.167,14.597 205.939,14.89 ; 206.143,-3.583 206.167,-3.559
Drill Drawing:
  drawing of 281 lines, arcs and shapes, not listed
  text "Fabrication Notes:" at -0.029,72.28 h1.78
  text "1. All dimensions in inches.  Tolerance = +/- 0.005\" unless noted otherwise" at -0.029,69.74 h1.14
  text "2. All materials: laminates, resins, metallizations and soldermask to be compliant to EU RoHS directive 2002/95/EC IAW SP-12509-01." at -0.029,67.835 h1.14
  text "3. Phenolic Paper FR-1 or similar grade." at -0.029,65.93 h1.14
  text "4. Adjust prepreg for 0.062\", +/- 0.003\" finished thickness measured over soldermask." at -0.029,64.025 h1.14
  text "5. Copper thickness 0.0014\", (1 oz)." at -0.029,62.12 h1.14
  text "Symbol" at 120.05,60.643 h1.83
  text "Hit Count" at 132.899,60.643 h1.83
  text "Finished Hole Size" at 150.624,60.643 h1.83
  text "Plated" at 184.802,60.643 h1.83
  text "Hole Type" at 197.651,60.643 h1.83
  text "6. Drill chart dimensions are drill sizes and not finished hole sizes." at -0.15,60.126 h1.14
  text "7. Finish - immersion gold over nickel.  No exposed bare copper permitted." at -0.15,58.221 h1.14
  text "2" at 132.899,56.833 h1.52
  text "0.584mm (23.00mil)" at 150.624,56.833 h1.52
  text "PTH" at 184.802,56.833 h1.52
  text "Round" at 197.651,56.833 h1.52
  text "8. Thieving not allowed on layer 1." at -0.15,56.316 h1.14
  text "9. Solder mask over bare copper, LPI class 2 gen. industrial registration +/- 0.004\"." at -0.15,54.411 h1.14
  text "10" at 132.899,53.023 h1.52
  text "0.650mm (25.59mil)" at 150.624,53.023 h1.52
  text "PTH" at 184.802,53.023 h1.52
  text "Round" at 197.651,53.023 h1.52
  text "10. No coverage on solder pads permitted." at -0.15,52.506 h1.14
  text "11. Refer to soldermask gerbers for tenting of vias." at -0.15,50.601 h1.14
  text "14" at 132.899,49.213 h1.52
  text "0.762mm (30.00mil)" at 150.624,49.213 h1.52
  text "PTH" at 184.802,49.213 h1.52
  text "Round" at 197.651,49.213 h1.52
  text "12. White silkscreen legend over green soldermask" at -0.15,48.696 h1.14
  text "13. Manufacturer icons not permitted on the silkscreen top layer." at -0.15,46.791 h1.14
  text "69" at 132.899,45.403 h1.52
  text "0.800mm (31.50mil)" at 150.624,45.403 h1.52
  text "PTH" at 184.802,45.403 h1.52
  text "Round" at 197.651,45.403 h1.52
  text "14. PCB serialization/panel placement ID on silkscreen bottom." at -0.15,44.886 h1.14
  text "15. Full electrical test against IPC-356A netlist." at -0.15,42.981 h1.14
  text "80" at 132.899,41.593 h1.52
  text "0.000mm (0.00mil)" at 150.624,41.593 h1.52
  text "PTH" at 184.802,41.593 h1.52
  text "Round" at 197.651,41.593 h1.52
  text "16. This is a single copper layer design with no copper permitted on the bottom side," at -0.143,40.921 h1.14
  text "(no copper pads for through hole components on bottom layer)" at 4.124,38.83 h1.14
  text "175 Total" at 132.899,37.783 h1.52
  text "17.  Do not plate through holes." at -0.168,37.205 h1.14
  text "Drill Drawing" at 1.495,-37.765 h2
  text "Layer" at 0.092,-54.034 h1.52
  text "Name" at 10.504,-54.034 h1.52
  text "Material" at 37.421,-54.034 h1.52
  text "Thickness" at 68.4,-54.034 h1.52
  text "Constant" at 84.906,-54.034 h1.52
  text "Board Layer Stack" at 99.38,-54.034 h1.52
  text "1" at 0.092,-57.082 h1.52
  text "Top Paste" at 10.504,-57.082 h1.52
  text "2" at 0.092,-60.13 h1.52
  text "Top Overlay" at 10.504,-60.13 h1.52
  text "3" at 0.092,-63.178 h1.52
  text "Top Solder" at 10.504,-63.178 h1.52
  text "Solder Resist" at 37.421,-63.178 h1.52
  text "0.40mil" at 68.4,-63.178 h1.52
  text "3.5" at 84.906,-63.178 h1.52
  text "4" at 0.092,-66.226 h1.52
  text "Top Layer" at 10.504,-66.226 h1.52
  text "Copper" at 37.421,-66.226 h1.52
  text "1.40mil" at 68.4,-66.226 h1.52
  text "5" at 0.092,-69.274 h1.52
  text "Dielectric1" at 10.504,-69.274 h1.52
  text "FR-1 Phenolic Paper" at 37.421,-69.274 h1.52
  text "12.60mil" at 68.4,-69.274 h1.52
  text "2.7" at 84.906,-69.274 h1.52
  text "6" at 0.092,-72.322 h1.52
  text "Carbon Ink Layer" at 10.504,-72.322 h1.52
  text "Copper" at 37.421,-72.322 h1.52
  text "7" at 0.092,-75.37 h1.52
  text "Bottom Solder" at 10.504,-75.37 h1.52
  text "FR-4" at 37.421,-75.37 h1.52
  text "12.60mil" at 68.4,-75.37 h1.52
  text "4.8" at 84.906,-75.37 h1.52
  text "8" at 0.092,-78.418 h1.52
  text "Bottom Overlay" at 10.504,-78.418 h1.52
  text "9" at 0.092,-81.466 h1.52
  text "Bottom Paste" at 10.504,-81.466 h1.52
